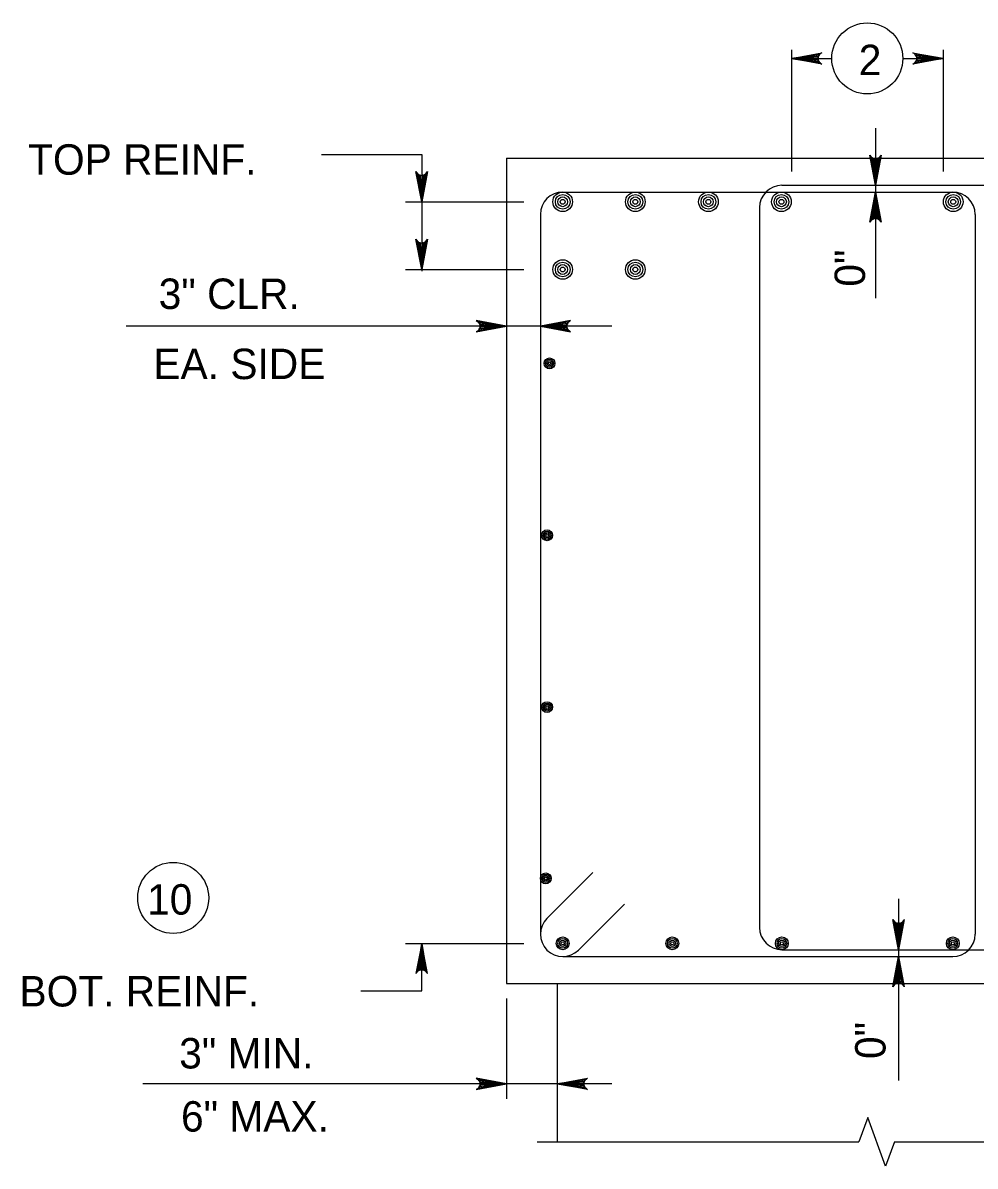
# Model space of a CAD drawing. Extents: x 646165 to 651486, y 296916 to 299292.
# Drawn here: x 648500.7 to 648594.6, y 298351 to 298463.7 of the extents above; entities that cross this region are included whole.
import ezdxf

# ---------------------------------------------------------------- set-up
doc = ezdxf.new("R2010")
doc.units = 0
for name, color, linetype in [('51', 7, 'Continuous'), ('52', 7, 'Continuous'), ('53', 7, 'Continuous'), ('54', 7, 'Continuous')]:
    doc.layers.add(name, color=color, linetype=linetype)

msp = doc.modelspace()

# ---------------------------------------------------------------- linework, layer by layer
at = {"layer": '51'}
for p, q in [((648548.38, 298450.37), (648548.38, 298369.03)), ((648548.38, 298450.37), (648619.5, 298450.37)), ((648548.38, 298369.03), (648619.5, 298369.03)), ((648553.38, 298369.03), (648553.38, 298353.45))]:
    msp.add_line(p, q, dxfattribs=at)
at = {"layer": '52'}
for p, q in [((648576.47, 298461.06), (648576.47, 298449.05)), ((648591.42, 298461.06), (648591.42, 298449.05)), ((648576.47, 298460.2), (648580.44, 298460.2)), ((648587.44, 298460.2), (648591.42, 298460.2)), ((648584.74, 298453.32), (648584.74, 298436.57)), ((648530.15, 298450.74), (648540.02, 298450.74)), ((648540.02, 298450.74), (648540.02, 298439.24)), ((648538.41, 298446.07), (648550.08, 298446.07)), ((648538.41, 298439.4), (648550.08, 298439.4)), ((648558.77, 298433.81), (648510.91, 298433.81)), ((648587.03, 298377.4), (648587.03, 298359.5)), ((648538.41, 298373), (648550.08, 298373)), ((648540.02, 298368.33), (648540.02, 298373)), ((648534.03, 298368.33), (648540.02, 298368.33)), ((648548.38, 298367.55), (648548.38, 298357.67)), ((648558.77, 298359.15), (648512.53, 298359.15)), ((648551.41, 298353.45), (648583.11, 298353.45)), ((648586.61, 298353.45), (648616.57, 298353.45))]:
    msp.add_line(p, q, dxfattribs=at)
for points in [[(648576.47, 298460.2), (648579.46, 298460.76), (648579.34, 298460.68), (648579.23, 298460.6), (648579.17, 298460.5), (648579.11, 298460.4), (648579.09, 298460.3), (648579.07, 298460.2), (648579.09, 298460.1), (648579.11, 298460), (648579.17, 298459.9), (648579.23, 298459.8), (648579.34, 298459.72), (648579.46, 298459.64), (648576.47, 298460.2), (648579.34, 298459.72), (648579.23, 298459.8), (648576.47, 298460.2), (648579.17, 298459.9), (648579.11, 298460), (648576.47, 298460.2), (648579.09, 298460.1), (648579.07, 298460.2), (648576.47, 298460.2), (648579.09, 298460.3), (648579.11, 298460.4), (648576.47, 298460.2), (648579.17, 298460.5), (648579.23, 298460.6), (648576.47, 298460.2), (648579.34, 298460.68)], [(648591.42, 298460.2), (648588.44, 298459.64), (648588.55, 298459.72), (648588.67, 298459.8), (648588.73, 298459.9), (648588.79, 298460), (648588.81, 298460.1), (648588.82, 298460.2), (648588.81, 298460.3), (648588.79, 298460.4), (648588.73, 298460.5), (648588.67, 298460.6), (648588.55, 298460.68), (648588.44, 298460.76), (648591.42, 298460.2), (648588.55, 298460.68), (648588.67, 298460.6), (648591.42, 298460.2), (648588.73, 298460.5), (648588.79, 298460.4), (648591.42, 298460.2), (648588.81, 298460.3), (648588.82, 298460.2), (648591.42, 298460.2), (648588.81, 298460.1), (648588.79, 298460), (648591.42, 298460.2), (648588.73, 298459.9), (648588.67, 298459.8), (648591.42, 298460.2), (648588.55, 298459.72)], [(648584.74, 298447.7), (648584.18, 298450.68), (648584.26, 298450.57), (648584.34, 298450.45), (648584.44, 298450.39), (648584.54, 298450.33), (648584.64, 298450.32), (648584.74, 298450.3), (648584.84, 298450.32), (648584.94, 298450.33), (648585.04, 298450.39), (648585.14, 298450.45), (648585.22, 298450.57), (648585.3, 298450.68), (648584.74, 298447.7), (648585.22, 298450.57), (648585.14, 298450.45), (648584.74, 298447.7), (648585.04, 298450.39), (648584.94, 298450.33), (648584.74, 298447.7), (648584.84, 298450.32), (648584.74, 298450.3), (648584.74, 298447.7), (648584.64, 298450.32), (648584.54, 298450.33), (648584.74, 298447.7), (648584.44, 298450.39), (648584.34, 298450.45), (648584.74, 298447.7), (648584.26, 298450.57)], [(648540.02, 298446.07), (648539.46, 298449.05), (648539.54, 298448.94), (648539.62, 298448.82), (648539.72, 298448.76), (648539.82, 298448.7), (648539.92, 298448.68), (648540.02, 298448.67), (648540.12, 298448.68), (648540.22, 298448.7), (648540.32, 298448.76), (648540.42, 298448.82), (648540.5, 298448.94), (648540.58, 298449.05), (648540.02, 298446.07), (648540.5, 298448.94), (648540.42, 298448.82), (648540.02, 298446.07), (648540.32, 298448.76), (648540.22, 298448.7), (648540.02, 298446.07), (648540.12, 298448.68), (648540.02, 298448.67), (648540.02, 298446.07), (648539.92, 298448.68), (648539.82, 298448.7), (648540.02, 298446.07), (648539.72, 298448.76), (648539.62, 298448.82), (648540.02, 298446.07), (648539.54, 298448.94)], [(648584.74, 298447.03), (648585.3, 298444.05), (648585.22, 298444.17), (648585.14, 298444.28), (648585.04, 298444.34), (648584.94, 298444.4), (648584.84, 298444.42), (648584.74, 298444.43), (648584.64, 298444.42), (648584.54, 298444.4), (648584.44, 298444.34), (648584.34, 298444.28), (648584.26, 298444.17), (648584.18, 298444.05), (648584.74, 298447.03), (648584.26, 298444.17), (648584.34, 298444.28), (648584.74, 298447.03), (648584.44, 298444.34), (648584.54, 298444.4), (648584.74, 298447.03), (648584.64, 298444.42), (648584.74, 298444.43), (648584.74, 298447.03), (648584.84, 298444.42), (648584.94, 298444.4), (648584.74, 298447.03), (648585.04, 298444.34), (648585.14, 298444.28), (648584.74, 298447.03), (648585.22, 298444.17)], [(648540.02, 298439.4), (648539.46, 298442.38), (648539.54, 298442.27), (648539.62, 298442.15), (648539.72, 298442.09), (648539.82, 298442.03), (648539.92, 298442.02), (648540.02, 298442), (648540.12, 298442.02), (648540.22, 298442.03), (648540.32, 298442.09), (648540.42, 298442.15), (648540.5, 298442.27), (648540.58, 298442.38), (648540.02, 298439.4), (648540.5, 298442.27), (648540.42, 298442.15), (648540.02, 298439.4), (648540.32, 298442.09), (648540.22, 298442.03), (648540.02, 298439.4), (648540.12, 298442.02), (648540.02, 298442), (648540.02, 298439.4), (648539.92, 298442.02), (648539.82, 298442.03), (648540.02, 298439.4), (648539.72, 298442.09), (648539.62, 298442.15), (648540.02, 298439.4), (648539.54, 298442.27)], [(648548.38, 298433.81), (648545.4, 298434.37), (648545.52, 298434.29), (648545.63, 298434.21), (648545.69, 298434.11), (648545.75, 298434.01), (648545.77, 298433.91), (648545.78, 298433.81), (648545.77, 298433.71), (648545.75, 298433.61), (648545.69, 298433.51), (648545.63, 298433.41), (648545.52, 298433.33), (648545.4, 298433.25), (648548.38, 298433.81), (648545.52, 298433.33), (648545.63, 298433.41), (648548.38, 298433.81), (648545.69, 298433.51), (648545.75, 298433.61), (648548.38, 298433.81), (648545.77, 298433.71), (648545.78, 298433.81), (648548.38, 298433.81), (648545.77, 298433.91), (648545.75, 298434.01), (648548.38, 298433.81), (648545.69, 298434.11), (648545.63, 298434.21), (648548.38, 298433.81), (648545.52, 298434.29)], [(648551.72, 298433.81), (648554.7, 298433.25), (648554.59, 298433.33), (648554.47, 298433.41), (648554.41, 298433.51), (648554.35, 298433.61), (648554.33, 298433.71), (648554.32, 298433.81), (648554.33, 298433.91), (648554.35, 298434.01), (648554.41, 298434.11), (648554.47, 298434.21), (648554.59, 298434.29), (648554.7, 298434.37), (648551.72, 298433.81), (648554.59, 298434.29), (648554.47, 298434.21), (648551.72, 298433.81), (648554.41, 298434.11), (648554.35, 298434.01), (648551.72, 298433.81), (648554.33, 298433.91), (648554.32, 298433.81), (648551.72, 298433.81), (648554.33, 298433.71), (648554.35, 298433.61), (648551.72, 298433.81), (648554.41, 298433.51), (648554.47, 298433.41), (648551.72, 298433.81), (648554.59, 298433.33)], [(648587.03, 298372.37), (648586.47, 298375.35), (648586.55, 298375.23), (648586.63, 298375.12), (648586.73, 298375.06), (648586.83, 298375), (648586.93, 298374.98), (648587.03, 298374.97), (648587.13, 298374.98), (648587.23, 298375), (648587.33, 298375.06), (648587.43, 298375.12), (648587.51, 298375.23), (648587.59, 298375.35), (648587.03, 298372.37), (648587.51, 298375.23), (648587.43, 298375.12), (648587.03, 298372.37), (648587.33, 298375.06), (648587.23, 298375), (648587.03, 298372.37), (648587.13, 298374.98), (648587.03, 298374.97), (648587.03, 298372.37), (648586.93, 298374.98), (648586.83, 298375), (648587.03, 298372.37), (648586.73, 298375.06), (648586.63, 298375.12), (648587.03, 298372.37), (648586.55, 298375.23)], [(648540.02, 298373), (648539.46, 298370.02), (648539.54, 298370.13), (648539.62, 298370.25), (648539.72, 298370.31), (648539.82, 298370.37), (648539.92, 298370.38), (648540.02, 298370.4), (648540.12, 298370.38), (648540.22, 298370.37), (648540.32, 298370.31), (648540.42, 298370.25), (648540.5, 298370.13), (648540.58, 298370.02), (648540.02, 298373), (648540.5, 298370.13), (648540.42, 298370.25), (648540.02, 298373), (648540.32, 298370.31), (648540.22, 298370.37), (648540.02, 298373), (648540.12, 298370.38), (648540.02, 298370.4), (648540.02, 298373), (648539.92, 298370.38), (648539.82, 298370.37), (648540.02, 298373), (648539.72, 298370.31), (648539.62, 298370.25), (648540.02, 298373), (648539.54, 298370.13)], [(648587.03, 298371.7), (648587.59, 298368.72), (648587.51, 298368.83), (648587.43, 298368.95), (648587.33, 298369.01), (648587.23, 298369.07), (648587.13, 298369.08), (648587.03, 298369.1), (648586.93, 298369.08), (648586.83, 298369.07), (648586.73, 298369.01), (648586.63, 298368.95), (648586.55, 298368.83), (648586.47, 298368.72), (648587.03, 298371.7), (648586.55, 298368.83), (648586.63, 298368.95), (648587.03, 298371.7), (648586.73, 298369.01), (648586.83, 298369.07), (648587.03, 298371.7), (648586.93, 298369.08), (648587.03, 298369.1), (648587.03, 298371.7), (648587.13, 298369.08), (648587.23, 298369.07), (648587.03, 298371.7), (648587.33, 298369.01), (648587.43, 298368.95), (648587.03, 298371.7), (648587.51, 298368.83)], [(648548.38, 298359.15), (648545.4, 298359.71), (648545.52, 298359.63), (648545.63, 298359.55), (648545.69, 298359.45), (648545.75, 298359.35), (648545.77, 298359.25), (648545.78, 298359.15), (648545.77, 298359.05), (648545.75, 298358.95), (648545.69, 298358.85), (648545.63, 298358.75), (648545.52, 298358.67), (648545.4, 298358.59), (648548.38, 298359.15), (648545.52, 298358.67), (648545.63, 298358.75), (648548.38, 298359.15), (648545.69, 298358.85), (648545.75, 298358.95), (648548.38, 298359.15), (648545.77, 298359.05), (648545.78, 298359.15), (648548.38, 298359.15), (648545.77, 298359.25), (648545.75, 298359.35), (648548.38, 298359.15), (648545.69, 298359.45), (648545.63, 298359.55), (648548.38, 298359.15), (648545.52, 298359.63)], [(648553.38, 298359.15), (648556.37, 298359.71), (648556.25, 298359.63), (648556.14, 298359.55), (648556.08, 298359.45), (648556.02, 298359.35), (648556, 298359.25), (648555.98, 298359.15), (648556, 298359.05), (648556.02, 298358.95), (648556.08, 298358.85), (648556.14, 298358.75), (648556.25, 298358.67), (648556.37, 298358.59), (648553.38, 298359.15), (648556.25, 298358.67), (648556.14, 298358.75), (648553.38, 298359.15), (648556.08, 298358.85), (648556.02, 298358.95), (648553.38, 298359.15), (648556, 298359.05), (648555.98, 298359.15), (648553.38, 298359.15), (648556, 298359.25), (648556.02, 298359.35), (648553.38, 298359.15), (648556.08, 298359.45), (648556.14, 298359.55), (648553.38, 298359.15), (648556.25, 298359.63)], [(648586.61, 298353.45), (648585.73, 298351.05), (648583.98, 298355.85), (648583.11, 298353.45)]]:
    msp.add_lwpolyline(points, dxfattribs=at)
for centre in [(648583.94, 298460.2), (648515.53, 298377.48)]:
    msp.add_circle(centre, 3.5, dxfattribs=at)
at = {"layer": '54'}
for p, q in [((648553.92, 298447.03), (648592.37, 298447.03)), ((648575.52, 298447.7), (648613.97, 298447.7)), ((648551.72, 298444.83), (648551.72, 298373.95)), ((648573.32, 298445.5), (648573.32, 298374.57)), ((648594.57, 298444.83), (648594.57, 298373.9)), ((648552.36, 298375.46), (648556.89, 298379.98)), ((648555.47, 298372.34), (648560, 298376.87)), ((648553.92, 298371.7), (648592.37, 298371.7)), ((648575.52, 298372.37), (648613.97, 298372.37))]:
    msp.add_line(p, q, dxfattribs=at)
for centre, radius in [((648553.92, 298446.07), 0.967), ((648553.92, 298446.07), 0.725), ((648561.08, 298446.07), 0.967), ((648561.08, 298446.07), 0.725), ((648568.28, 298446.07), 0.967), ((648568.28, 298446.07), 0.725), ((648575.48, 298446.07), 0.967), ((648575.48, 298446.07), 0.725), ((648592.41, 298446.07), 0.967), ((648592.41, 298446.07), 0.725), ((648553.92, 298446.07), 0.483), ((648553.92, 298446.07), 0.242), ((648561.08, 298446.07), 0.483), ((648561.08, 298446.07), 0.242), ((648568.28, 298446.07), 0.483), ((648568.28, 298446.07), 0.242), ((648575.48, 298446.07), 0.483), ((648575.48, 298446.07), 0.242), ((648592.41, 298446.07), 0.483), ((648592.41, 298446.07), 0.242), ((648553.92, 298439.4), 0.967), ((648553.92, 298439.4), 0.725), ((648561.08, 298439.4), 0.967), ((648561.08, 298439.4), 0.725), ((648553.92, 298439.4), 0.483), ((648553.92, 298439.4), 0.242), ((648561.08, 298439.4), 0.483), ((648561.08, 298439.4), 0.242), ((648552.62, 298430.15), 0.533), ((648552.62, 298430.15), 0.4), ((648552.62, 298430.15), 0.267), ((648552.62, 298430.15), 0.133), ((648552.38, 298413.21), 0.533), ((648552.38, 298413.21), 0.4), ((648552.38, 298413.21), 0.267), ((648552.38, 298413.21), 0.133), ((648552.38, 298396.28), 0.533), ((648552.38, 298396.28), 0.4), ((648552.38, 298396.28), 0.267), ((648552.38, 298396.28), 0.133), ((648552.25, 298379.4), 0.533), ((648552.25, 298379.4), 0.4), ((648552.25, 298379.4), 0.267), ((648552.25, 298379.4), 0.133), ((648553.92, 298373), 0.633), ((648564.72, 298373), 0.633), ((648575.52, 298373), 0.633), ((648592.37, 298373), 0.633), ((648553.92, 298373), 0.475), ((648553.92, 298373), 0.317), ((648553.92, 298373), 0.158), ((648564.72, 298373), 0.475), ((648564.72, 298373), 0.317), ((648564.72, 298373), 0.158), ((648575.52, 298373), 0.475), ((648575.52, 298373), 0.317), ((648575.52, 298373), 0.158), ((648592.37, 298373), 0.475), ((648592.37, 298373), 0.317), ((648592.37, 298373), 0.158)]:
    msp.add_circle(centre, radius, dxfattribs=at)
for centre, start, end in [((648553.92, 298444.83), 90, 180), ((648575.52, 298445.5), 90, 180), ((648592.37, 298444.83), 0, 90), ((648553.92, 298373.9), 135, 315), ((648575.52, 298374.57), 180, 270), ((648592.37, 298373.9), 270, 0)]:
    msp.add_arc(centre, 2.2, start, end, dxfattribs=at)

# ---------------------------------------------------------------- texts
at = {"layer": '53'}
for s, p in [('2', (648583.1, 298458.55)), ('TOP REINF.', (648501.23, 298448.74)), ('3" CLR.', (648514.1, 298435.51)), ('EA. SIDE', (648513.58, 298428.6)), ('10', (648512.96, 298375.83)), ('BOT. REINF.', (648500.38, 298366.78)), ('3" MIN.', (648516.12, 298360.67)), ('6" MAX.', (648516.3, 298354.45))]:
    msp.add_text(s, height=3, dxfattribs=at).set_placement(p)
for p in [(648583.72, 298437.71), (648585.74, 298361.6)]:
    msp.add_text('0"', height=3, rotation=90, dxfattribs=at).set_placement(p)

doc.saveas('drawing.dxf')
